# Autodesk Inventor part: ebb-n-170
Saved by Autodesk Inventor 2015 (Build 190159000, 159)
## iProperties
Created: 2020-07
Part Number: ebb-n-170
Checked By: TraceParts S.A.
Material: Generic
Catalog Web Link: www.traceparts.com
Document SubType Name: Modeling
Designer: TraceParts
Density: 1 g/cm^3
Appearance: Default
Company: TraceParts S.A.
Author: TraceParts
REFERENCE: EBB-N-170
DESIGN: EBB-N-170
SUPPLIER: Soler & Palau
TraceParts.PartNumber: 10-04022019-080771
TraceParts.PartTitle: EBB-N
TraceParts.InstanceId: 10-04022019-0807719YW1Z7VCBZWDGEGOKEROL9CG7
TraceParts.PartStatus: Published
TraceParts.PartVersion: 1.0.1
TRACEPARTS: TRACEPARTS
TraceParts.PartLanguage: en
TraceParts.ClassPath: SOLER_PALAU:10-04022019-080771
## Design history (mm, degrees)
feature "ebb-n-170"
body "Solid1"
